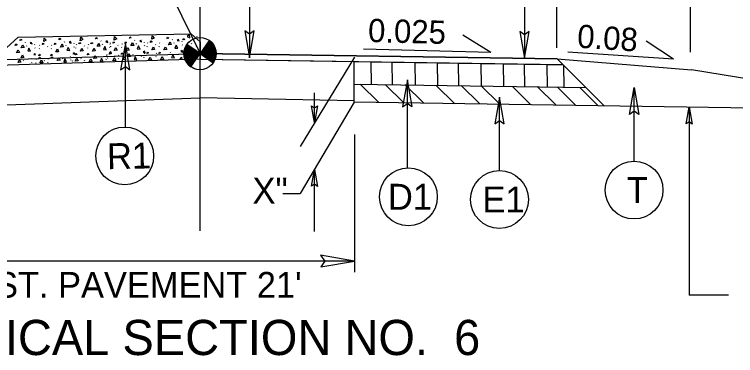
# Model space of a CAD drawing. Extents: x 2176156 to 2177167, y 76401 to 76644.
# Drawn here: x 2177099.84 to 2177132.18, y 76502.12 to 76517.41 of the extents above; entities that cross this region are included whole.
import ezdxf

# ---------------------------------------------------------------- set-up
doc = ezdxf.new("R2010")
doc.units = 0
for name, color, linetype in [('Exist Building', 7, 'Continuous'), ('Exist Building Metal Canopy', 7, 'Continuous'), ('Exist Roads Change in Surface', 7, 'Continuous'), ('Exist Roads Curbs', 7, 'Continuous'), ('Exist Roads EOP Other', 7, 'Continuous'), ('Exist Roads Soil', 7, 'Continuous'), ('Exist Structure Minor Culvert Topo', 7, 'Continuous'), ('Exist Utilities Other Pole CELL', 7, 'Continuous'), ('Model Boundary Lines Text', 7, 'Continuous'), ('Old_Level_1', 7, 'Continuous'), ('Old_Level_3', 7, 'Continuous'), ('Prop North Arrow NAD83 for Plan Sheets CELL', 7, 'Continuous'), ('Sheet Plan CELL', 7, 'Continuous')]:
    doc.layers.add(name, color=color, linetype=linetype)

msp = doc.modelspace()

# ---------------------------------------------------------------- linework, layer by layer
at = {"layer": 'Exist Building'}
for p, q in [((2177115.083, 76513.476), (2177115.083, 76515.298)), ((2177141.279, 76513.086), (2177115.083, 76513.476))]:
    msp.add_line(p, q, dxfattribs=at)
at = {"layer": 'Exist Roads Change in Surface'}
for p, q in [((2177100.315, 76516.153), (2177100.325, 76516.137)), ((2177102.072, 76516.188), (2177102.083, 76516.172)), ((2177102.507, 76516.103), (2177102.496, 76516.087)), ((2177103.714, 76516.221), (2177103.725, 76516.205)), ((2177104.148, 76516.135), (2177104.137, 76516.119)), ((2177105.229, 76516.251), (2177105.24, 76516.235)), ((2177105.664, 76516.166), (2177105.653, 76516.15)), ((2177105.81, 76516.132), (2177105.821, 76516.116)), ((2177106.35, 76516.132), (2177106.36, 76516.116)), ((2177106.918, 76516.285), (2177106.928, 76516.269)), ((2177106.993, 76516.132), (2177106.982, 76516.116)), ((2177107.352, 76516.2), (2177107.341, 76516.184)), ((2177107.788, 76516.08), (2177107.777, 76516.104)), ((2177108.03, 76516.389), (2177108.019, 76516.413)), ((2177108.575, 76516.243), (2177108.163, 76515.651)), ((2177100.39, 76516), (2177100.379, 76515.984)), ((2177100.749, 76516.067), (2177100.738, 76516.051)), ((2177100.769, 76515.892), (2177100.758, 76515.916)), ((2177100.945, 76515.86), (2177100.955, 76515.884)), ((2177100.965, 76516.035), (2177100.976, 76516.019)), ((2177101.324, 76515.967), (2177101.334, 76515.951)), ((2177101.484, 76515.86), (2177101.495, 76515.884)), ((2177101.504, 76516.035), (2177101.515, 76516.019)), ((2177102.148, 76516.035), (2177102.137, 76516.019)), ((2177102.527, 76515.927), (2177102.516, 76515.951)), ((2177102.586, 76515.892), (2177102.597, 76515.916)), ((2177102.607, 76516.068), (2177102.617, 76516.052)), ((2177102.965, 76516), (2177102.976, 76515.984)), ((2177103.126, 76515.892), (2177103.136, 76515.916)), ((2177103.146, 76516.068), (2177103.157, 76516.052)), ((2177103.789, 76516.068), (2177103.779, 76516.052)), ((2177104.102, 76515.923), (2177104.112, 76515.947)), ((2177104.122, 76516.098), (2177104.133, 76516.082)), ((2177104.168, 76515.96), (2177104.158, 76515.984)), ((2177104.481, 76516.03), (2177104.491, 76516.014)), ((2177104.641, 76515.923), (2177104.652, 76515.947)), ((2177104.661, 76516.098), (2177104.672, 76516.082)), ((2177105.305, 76516.098), (2177105.294, 76516.082)), ((2177105.684, 76515.99), (2177105.673, 76516.014)), ((2177105.79, 76515.956), (2177105.801, 76515.98)), ((2177106.169, 76516.064), (2177106.18, 76516.048)), ((2177106.329, 76515.956), (2177106.34, 76515.98)), ((2177107.372, 76516.024), (2177107.361, 76516.048)), ((2177108.163, 76515.651), (2177107.572, 76516.063)), ((2177107.67, 76515.792), (2177107.66, 76515.776)), ((2177108.003, 76515.963), (2177107.993, 76515.987)), ((2177102.355, 76515.52), (2177102.344, 76515.504)), ((2177102.456, 76515.489), (2177102.467, 76515.473)), ((2177102.995, 76515.507), (2177103.006, 76515.492)), ((2177103.638, 76515.528), (2177103.628, 76515.512)), ((2177103.969, 76515.57), (2177103.981, 76515.555)), ((2177103.994, 76515.608), (2177103.984, 76515.592)), ((2177104.02, 76515.433), (2177104.009, 76515.457)), ((2177104.33, 76515.514), (2177104.341, 76515.499)), ((2177104.508, 76515.588), (2177104.52, 76515.573)), ((2177105.151, 76515.61), (2177105.141, 76515.593)), ((2177105.534, 76515.515), (2177105.522, 76515.538)), ((2177105.641, 76515.484), (2177105.651, 76515.509)), ((2177105.655, 76515.661), (2177105.667, 76515.645)), ((2177106.016, 76515.605), (2177106.028, 76515.589)), ((2177106.18, 76515.502), (2177106.19, 76515.527)), ((2177106.195, 76515.679), (2177106.206, 76515.663)), ((2177106.838, 76515.7), (2177106.827, 76515.684)), ((2177107.22, 76515.605), (2177107.209, 76515.628)), ((2177107.752, 76515.059), (2177108.163, 76515.651)), ((2177108.756, 76515.241), (2177108.163, 76515.651)), ((2177108.163, 76515.651), (2177108.756, 76515.241)), ((2177100.243, 76515.347), (2177100.232, 76515.33)), ((2177100.599, 76515.426), (2177100.589, 76515.41)), ((2177100.625, 76515.251), (2177100.614, 76515.275)), ((2177100.802, 76515.225), (2177100.812, 76515.249)), ((2177100.816, 76515.401), (2177100.827, 76515.386)), ((2177101.177, 76515.346), (2177101.188, 76515.33)), ((2177101.341, 76515.243), (2177101.351, 76515.268)), ((2177101.355, 76515.419), (2177101.367, 76515.404)), ((2177101.998, 76515.441), (2177101.988, 76515.424)), ((2177102.381, 76515.346), (2177102.369, 76515.369)), ((2177102.441, 76515.313), (2177102.451, 76515.337)), ((2177102.817, 76515.433), (2177102.828, 76515.418)), ((2177102.981, 76515.331), (2177102.99, 76515.355)), ((2177103.955, 76515.394), (2177103.965, 76515.418)), ((2177104.494, 76515.412), (2177104.504, 76515.436))]:
    msp.add_line(p, q, dxfattribs=at)
for points in [[(2177105.996, 76516.294), (2177106.017, 76516.446), (2177106.112, 76516.347), (2177105.998, 76516.294)], [(2177107.706, 76516.361), (2177107.685, 76516.513), (2177107.589, 76516.415), (2177107.703, 76516.362)], [(2177100.078, 76516.239), (2177100.11, 76516.306), (2177100.163, 76516.266), (2177100.078, 76516.239)], [(2177100.626, 76516.086), (2177100.595, 76516.153), (2177100.541, 76516.113), (2177100.626, 76516.086)], [(2177101.087, 76516.054), (2177101.119, 76516.12), (2177101.172, 76516.08), (2177101.087, 76516.054)], [(2177101.15, 76516.197), (2177101.171, 76516.349), (2177101.267, 76516.25), (2177101.153, 76516.198)], [(2177101.627, 76516.054), (2177101.659, 76516.12), (2177101.712, 76516.08), (2177101.627, 76516.054)], [(2177101.836, 76516.274), (2177101.868, 76516.341), (2177101.921, 76516.301), (2177101.836, 76516.274)], [(2177102.384, 76516.121), (2177102.352, 76516.188), (2177102.299, 76516.148), (2177102.384, 76516.121)], [(2177102.729, 76516.087), (2177102.761, 76516.153), (2177102.814, 76516.113), (2177102.729, 76516.087)], [(2177102.792, 76516.229), (2177102.813, 76516.382), (2177102.908, 76516.283), (2177102.794, 76516.23)], [(2177103.268, 76516.087), (2177103.3, 76516.153), (2177103.353, 76516.113), (2177103.268, 76516.087)], [(2177103.477, 76516.307), (2177103.509, 76516.373), (2177103.563, 76516.334), (2177103.477, 76516.307)], [(2177103.544, 76515.98), (2177103.616, 76516.115), (2177103.672, 76515.99), (2177103.547, 76515.98)], [(2177104.026, 76516.154), (2177103.994, 76516.221), (2177103.941, 76516.181), (2177104.026, 76516.154)], [(2177104.244, 76516.117), (2177104.276, 76516.183), (2177104.329, 76516.143), (2177104.244, 76516.117)], [(2177104.307, 76516.26), (2177104.328, 76516.412), (2177104.424, 76516.314), (2177104.31, 76516.261)], [(2177104.784, 76516.117), (2177104.816, 76516.183), (2177104.869, 76516.143), (2177104.784, 76516.117)], [(2177104.993, 76516.337), (2177105.025, 76516.404), (2177105.078, 76516.364), (2177104.993, 76516.337)], [(2177105.059, 76516.01), (2177105.131, 76516.146), (2177105.187, 76516.021), (2177105.062, 76516.01)], [(2177105.541, 76516.184), (2177105.509, 76516.251), (2177105.456, 76516.211), (2177105.541, 76516.184)], [(2177105.932, 76516.151), (2177105.964, 76516.217), (2177106.018, 76516.177), (2177105.932, 76516.151)], [(2177106.676, 76516.324), (2177106.708, 76516.391), (2177106.761, 76516.351), (2177106.676, 76516.324)], [(2177106.748, 76516.044), (2177106.82, 76516.179), (2177106.875, 76516.054), (2177106.75, 76516.044)], [(2177107.23, 76516.218), (2177107.198, 76516.285), (2177107.144, 76516.245), (2177107.23, 76516.218)], [(2177107.393, 76516.262), (2177107.425, 76516.328), (2177107.478, 76516.288), (2177107.393, 76516.262)], [(2177108.483, 76516.11), (2177108.856, 76515.85)], [(2177108.491, 76516.122), (2177108.85, 76515.872)], [(2177108.499, 76516.134), (2177108.842, 76515.895)], [(2177108.507, 76516.145), (2177108.834, 76515.919)], [(2177108.516, 76516.157), (2177108.823, 76515.943)], [(2177108.524, 76516.169), (2177108.811, 76515.97)], [(2177108.532, 76516.181), (2177108.796, 76515.997)], [(2177108.54, 76516.193), (2177108.78, 76516.026)], [(2177108.549, 76516.205), (2177108.76, 76516.057)], [(2177108.557, 76516.217), (2177108.733, 76516.094)], [(2177108.565, 76516.228), (2177108.699, 76516.135)], [(2177108.573, 76516.24), (2177108.638, 76516.195)], [(2177099.869, 76516.019), (2177099.901, 76516.085), (2177099.954, 76516.045), (2177099.869, 76516.019)], [(2177099.935, 76515.691), (2177100.007, 76515.827), (2177100.063, 76515.702), (2177099.938, 76515.691)], [(2177100.145, 76515.912), (2177100.216, 76516.047), (2177100.272, 76515.922), (2177100.147, 76515.912)], [(2177100.56, 76515.759), (2177100.488, 76515.895), (2177100.432, 76515.769), (2177100.557, 76515.759)], [(2177101.693, 76515.726), (2177101.765, 76515.862), (2177101.821, 76515.737), (2177101.696, 76515.726)], [(2177101.902, 76515.947), (2177101.974, 76516.083), (2177102.03, 76515.957), (2177101.905, 76515.947)], [(2177102.318, 76515.794), (2177102.246, 76515.93), (2177102.19, 76515.805), (2177102.315, 76515.794)], [(2177102.795, 76515.759), (2177102.867, 76515.895), (2177102.923, 76515.77), (2177102.798, 76515.759)], [(2177103.335, 76515.759), (2177103.407, 76515.895), (2177103.463, 76515.77), (2177103.337, 76515.759)], [(2177103.959, 76515.827), (2177103.887, 76515.963), (2177103.831, 76515.837), (2177103.957, 76515.827)], [(2177104.311, 76515.79), (2177104.383, 76515.925), (2177104.439, 76515.8), (2177104.313, 76515.79)], [(2177104.85, 76515.79), (2177104.922, 76515.925), (2177104.978, 76515.8), (2177104.853, 76515.79)], [(2177105.475, 76515.857), (2177105.403, 76515.993), (2177105.347, 76515.868), (2177105.472, 76515.857)], [(2177105.999, 76515.823), (2177106.071, 76515.959), (2177106.127, 76515.834), (2177106.002, 76515.823)], [(2177106.538, 76515.823), (2177106.61, 76515.959), (2177106.666, 76515.834), (2177106.541, 76515.823)], [(2177107.163, 76515.891), (2177107.091, 76516.027), (2177107.035, 76515.901), (2177107.16, 76515.891)], [(2177107.391, 76515.723), (2177107.359, 76515.79), (2177107.305, 76515.75), (2177107.391, 76515.723)], [(2177107.456, 76515.784), (2177107.995, 76515.409)], [(2177107.459, 76515.8), (2177108.003, 76515.421)], [(2177107.462, 76515.815), (2177108.012, 76515.433)], [(2177107.465, 76515.831), (2177108.02, 76515.445)], [(2177107.469, 76515.845), (2177108.028, 76515.457)], [(2177107.474, 76515.86), (2177108.036, 76515.468)], [(2177107.478, 76515.875), (2177108.045, 76515.48)], [(2177107.483, 76515.888), (2177108.053, 76515.492)], [(2177107.488, 76515.903), (2177108.061, 76515.504)], [(2177107.493, 76515.916), (2177108.069, 76515.516)], [(2177107.499, 76515.93), (2177108.077, 76515.528)], [(2177107.504, 76515.944), (2177108.086, 76515.539)], [(2177107.51, 76515.957), (2177108.094, 76515.551)], [(2177107.517, 76515.97), (2177108.102, 76515.563)], [(2177107.524, 76515.983), (2177108.11, 76515.575)], [(2177107.531, 76515.996), (2177108.119, 76515.587)], [(2177107.538, 76516.008), (2177108.127, 76515.599)], [(2177107.545, 76516.021), (2177108.135, 76515.61)], [(2177107.553, 76516.033), (2177108.143, 76515.622)], [(2177107.56, 76516.046), (2177108.152, 76515.634)], [(2177107.568, 76516.058), (2177107.568, 76516.058), (2177108.16, 76515.646)], [(2177108.252, 76515.779), (2177108.829, 76515.377)], [(2177108.26, 76515.79), (2177108.835, 76515.391)], [(2177108.269, 76515.802), (2177108.841, 76515.404)], [(2177108.277, 76515.814), (2177108.845, 76515.419)], [(2177108.285, 76515.826), (2177108.851, 76515.433)], [(2177108.293, 76515.838), (2177108.855, 76515.447)], [(2177108.302, 76515.85), (2177108.859, 76515.462)], [(2177108.31, 76515.862), (2177108.863, 76515.476)], [(2177108.318, 76515.873), (2177108.866, 76515.492)], [(2177108.326, 76515.885), (2177108.869, 76515.507)], [(2177108.335, 76515.897), (2177108.872, 76515.523)], [(2177108.343, 76515.909), (2177108.875, 76515.538)], [(2177108.351, 76515.921), (2177108.878, 76515.554)], [(2177108.359, 76515.932), (2177108.88, 76515.57)], [(2177108.368, 76515.944), (2177108.882, 76515.587)], [(2177108.376, 76515.956), (2177108.883, 76515.603)], [(2177108.384, 76515.968), (2177108.884, 76515.62)], [(2177108.392, 76515.98), (2177108.884, 76515.638)], [(2177108.4, 76515.992), (2177108.884, 76515.655)], [(2177108.409, 76516.003), (2177108.885, 76515.672)], [(2177108.417, 76516.015), (2177108.884, 76515.69)], [(2177108.425, 76516.027), (2177108.883, 76515.709)], [(2177108.433, 76516.039), (2177108.88, 76515.728)], [(2177108.442, 76516.051), (2177108.878, 76515.747)], [(2177108.45, 76516.063), (2177108.876, 76515.766)], [(2177108.458, 76516.075), (2177108.872, 76515.786)], [(2177108.466, 76516.086), (2177108.867, 76515.807)], [(2177108.475, 76516.098), (2177108.862, 76515.828)], [(2177100.134, 76515.461), (2177100.206, 76515.597), (2177100.262, 76515.471), (2177100.136, 76515.461)], [(2177100.788, 76515.591), (2177100.756, 76515.657), (2177100.702, 76515.617), (2177100.788, 76515.591)], [(2177100.926, 76515.559), (2177100.958, 76515.625), (2177101.011, 76515.585), (2177100.926, 76515.559)], [(2177100.938, 76515.424), (2177100.967, 76515.492), (2177101.022, 76515.453), (2177100.938, 76515.424)], [(2177101.466, 76515.559), (2177101.498, 76515.625), (2177101.551, 76515.585), (2177101.466, 76515.559)], [(2177101.477, 76515.442), (2177101.507, 76515.51), (2177101.561, 76515.471), (2177101.477, 76515.442)], [(2177101.756, 76515.344), (2177101.823, 76515.482), (2177101.883, 76515.359), (2177101.759, 76515.344)], [(2177102.545, 76515.626), (2177102.513, 76515.693), (2177102.46, 76515.653), (2177102.545, 76515.626)], [(2177102.568, 76515.591), (2177102.6, 76515.658), (2177102.653, 76515.618), (2177102.568, 76515.591)], [(2177103.107, 76515.591), (2177103.139, 76515.658), (2177103.192, 76515.618), (2177103.107, 76515.591)], [(2177103.396, 76515.432), (2177103.463, 76515.57), (2177103.523, 76515.447), (2177103.398, 76515.432)], [(2177104.083, 76515.622), (2177104.115, 76515.688), (2177104.168, 76515.648), (2177104.083, 76515.622)], [(2177104.187, 76515.659), (2177104.155, 76515.725), (2177104.102, 76515.685), (2177104.187, 76515.659)], [(2177104.257, 76515.326), (2177104.325, 76515.464), (2177104.385, 76515.341), (2177104.26, 76515.326)], [(2177104.623, 76515.622), (2177104.655, 76515.688), (2177104.708, 76515.648), (2177104.623, 76515.622)], [(2177104.707, 76515.367), (2177104.775, 76515.505), (2177104.835, 76515.382), (2177104.71, 76515.367)], [(2177104.909, 76515.513), (2177104.976, 76515.651), (2177105.037, 76515.528), (2177104.912, 76515.513)], [(2177105.329, 76515.374), (2177105.253, 76515.508), (2177105.201, 76515.381), (2177105.327, 76515.374)], [(2177105.702, 76515.689), (2177105.67, 76515.756), (2177105.617, 76515.716), (2177105.702, 76515.689)], [(2177105.771, 76515.655), (2177105.803, 76515.722), (2177105.857, 76515.682), (2177105.771, 76515.655)], [(2177105.855, 76515.358), (2177105.922, 76515.496), (2177105.982, 76515.373), (2177105.857, 76515.358)], [(2177106.311, 76515.655), (2177106.343, 76515.722), (2177106.396, 76515.682), (2177106.311, 76515.655)], [(2177106.394, 76515.376), (2177106.461, 76515.515), (2177106.521, 76515.391), (2177106.396, 76515.376)], [(2177107.016, 76515.465), (2177106.939, 76515.598), (2177106.887, 76515.471), (2177107.013, 76515.465)], [(2177107.281, 76515.422), (2177107.313, 76515.489), (2177107.367, 76515.449), (2177107.281, 76515.422)], [(2177107.443, 76515.688), (2177107.946, 76515.338)], [(2177107.443, 76515.67), (2177107.937, 76515.326)], [(2177107.443, 76515.653), (2177107.929, 76515.315)], [(2177107.443, 76515.618), (2177107.913, 76515.291)], [(2177107.444, 76515.635), (2177107.921, 76515.303)], [(2177107.444, 76515.599), (2177107.904, 76515.279)], [(2177107.445, 76515.704), (2177107.954, 76515.35)], [(2177107.447, 76515.721), (2177107.962, 76515.362)], [(2177107.447, 76515.58), (2177107.896, 76515.267)], [(2177107.448, 76515.737), (2177107.97, 76515.374)], [(2177107.449, 76515.561), (2177107.888, 76515.255)], [(2177107.45, 76515.753), (2177107.979, 76515.385)], [(2177107.451, 76515.542), (2177107.88, 76515.244)], [(2177107.453, 76515.769), (2177107.987, 76515.397)], [(2177107.455, 76515.522), (2177107.872, 76515.232)], [(2177107.458, 76515.502), (2177107.863, 76515.22)], [(2177107.463, 76515.481), (2177107.855, 76515.208)], [(2177107.469, 76515.459), (2177107.847, 76515.196)], [(2177108.17, 76515.66), (2177108.762, 76515.249), (2177108.762, 76515.249)], [(2177108.178, 76515.672), (2177108.77, 76515.26)], [(2177108.186, 76515.684), (2177108.777, 76515.273)], [(2177108.195, 76515.696), (2177108.785, 76515.285)], [(2177108.203, 76515.708), (2177108.792, 76515.298)], [(2177108.211, 76515.719), (2177108.799, 76515.311)], [(2177108.219, 76515.731), (2177108.806, 76515.323)], [(2177108.228, 76515.743), (2177108.811, 76515.337)], [(2177108.236, 76515.755), (2177108.818, 76515.35)], [(2177108.244, 76515.767), (2177108.824, 76515.363)], [(2177100, 76515.25), (2177100.068, 76515.388), (2177100.128, 76515.265), (2177100.003, 76515.25)], [(2177100.981, 76515.233), (2177101.053, 76515.369), (2177101.109, 76515.243), (2177100.983, 76515.233)], [(2177102.176, 76515.279), (2177102.1, 76515.413), (2177102.048, 76515.286), (2177102.174, 76515.279)], [(2177102.568, 76515.31), (2177102.635, 76515.448), (2177102.695, 76515.325), (2177102.57, 76515.31)], [(2177103.194, 76515.285), (2177103.261, 76515.423), (2177103.321, 76515.299), (2177103.197, 76515.285)], [(2177103.816, 76515.293), (2177103.739, 76515.427), (2177103.688, 76515.3), (2177103.813, 76515.293)], [(2177107.476, 76515.437), (2177107.839, 76515.184)], [(2177107.483, 76515.414), (2177107.83, 76515.173)], [(2177107.492, 76515.39), (2177107.822, 76515.161)], [(2177107.502, 76515.366), (2177107.814, 76515.149)], [(2177107.514, 76515.34), (2177107.806, 76515.137)], [(2177107.527, 76515.314), (2177107.797, 76515.125)], [(2177107.543, 76515.284), (2177107.789, 76515.113)], [(2177107.563, 76515.253), (2177107.781, 76515.102)], [(2177107.587, 76515.219), (2177107.773, 76515.09)], [(2177107.62, 76515.179), (2177107.765, 76515.078)], [(2177107.672, 76515.125), (2177107.756, 76515.066)]]:
    msp.add_lwpolyline(points, dxfattribs=at)
msp.add_circle((2177108.164, 76515.652), 0.721, dxfattribs=at)
for start, end in [(325.1751, 55.1751), (145.1751, 235.1751)]:
    msp.add_arc((2177108.164, 76515.652), 0.721, start, end, dxfattribs=at)
at = {"layer": 'Exist Roads Curbs'}
for p, q in [((2177099.488, 76515.381), (2177108.163, 76515.651)), ((2177108.163, 76515.651), (2177124.177, 76515.413)), ((2177124.176, 76515.414), (2177108.163, 76515.651)), ((2177108.163, 76515.651), (2177108.163, 76515.401)), ((2177108.163, 76515.401), (2177083.187, 76514.622)), ((2177108.163, 76515.401), (2177124.432, 76515.159)), ((2177123.731, 76515.171), (2177123.731, 76515.17)), ((2177123.731, 76515.17), (2177124.432, 76515.159)), ((2177124.432, 76515.159), (2177124.176, 76515.414))]:
    msp.add_line(p, q, dxfattribs=at)
for points in [[(2177108.163, 76515.401), (2177115.083, 76515.298), (2177115.845, 76515.287), (2177116.785, 76515.273), (2177117.818, 76515.258), (2177118.816, 76515.243), (2177119.756, 76515.229), (2177120.776, 76515.214), (2177121.773, 76515.199), (2177122.713, 76515.185), (2177123.731, 76515.17)], [(2177123.731, 76515.17), (2177123.731, 76515.171)]]:
    msp.add_lwpolyline(points, dxfattribs=at)
at = {"layer": 'Exist Roads EOP Other'}
msp.add_line((2177124.176, 76515.414), (2177130.212, 76514.931), dxfattribs=at)
at = {"layer": 'Exist Roads Soil'}
for p, q in [((2177100.005, 76516.388), (2177107.772, 76516.543)), ((2177108.163, 76516.182), (2177107.772, 76516.543)), ((2177099.488, 76515.912), (2177100.005, 76516.388)), ((2177108.163, 76516.182), (2177108.163, 76515.401)), ((2177124.176, 76515.414), (2177126.293, 76513.309)), ((2177158.163, 76510.272), (2177130.212, 76514.931)), ((2177115.095, 76514.282), (2177125.47, 76514.128))]:
    msp.add_line(p, q, dxfattribs=at)
at = {"layer": 'Exist Utilities Other Pole CELL'}
for p, q in [((2177121.213, 76515.706), (2177119.957, 76516.476)), ((2177129.404, 76515.397), (2177128.179, 76516.216)), ((2177121.213, 76515.706), (2177115.488, 76515.856)), ((2177129.404, 76515.397), (2177124.658, 76515.71))]:
    msp.add_line(p, q, dxfattribs=at)
at = {"layer": 'Model Boundary Lines Text'}
for p, q in [((2177115.86, 76514.273), (2177115.845, 76515.298)), ((2177116.8, 76514.265), (2177116.785, 76515.279)), ((2177117.833, 76514.252), (2177117.818, 76515.264)), ((2177118.83, 76514.228), (2177118.815, 76515.254)), ((2177119.77, 76514.221), (2177119.756, 76515.235)), ((2177120.79, 76514.2), (2177120.776, 76515.211)), ((2177121.788, 76514.176), (2177121.773, 76515.201)), ((2177122.728, 76514.169), (2177122.713, 76515.182)), ((2177123.746, 76514.155), (2177123.731, 76515.171)), ((2177124.489, 76514.142), (2177124.475, 76515.116)), ((2177116.182, 76513.455), (2177115.341, 76514.278)), ((2177117.301, 76513.451), (2177116.466, 76514.269)), ((2177118.186, 76513.447), (2177117.35, 76514.266)), ((2177119.594, 76513.406), (2177118.758, 76514.225)), ((2177120.713, 76513.402), (2177119.877, 76514.221)), ((2177121.599, 76513.397), (2177120.764, 76514.215)), ((2177123.007, 76513.356), (2177122.172, 76514.174)), ((2177124.127, 76513.352), (2177123.291, 76514.171)), ((2177125.02, 76513.333), (2177124.193, 76514.144)), ((2177126.01, 76513.333), (2177125.195, 76514.132))]:
    msp.add_line(p, q, dxfattribs=at)
at = {"layer": 'Old_Level_1'}
for points in [[(2177113.428, 76513.313), (2177113.295, 76512.559), (2177113.163, 76513.318), (2177113.297, 76513.221)], [(2177129.966, 76512.498), (2177130.096, 76513.252), (2177130.23, 76512.493), (2177130.096, 76512.59)], [(2177113.163, 76509.703), (2177113.295, 76510.457), (2177113.427, 76509.698), (2177113.293, 76509.794)], [(2177113.576, 76506.092), (2177115.086, 76506.352), (2177113.568, 76506.62), (2177113.761, 76506.352)]]:
    msp.add_lwpolyline(points, close=True, dxfattribs=at)
at = {"layer": 'Old_Level_3'}
for p, q in [((2177130.163, 76515.709), (2177130.163, 76530.14)), ((2177108.163, 76507.712), (2177108.163, 76526.159)), ((2177124.163, 76515.918), (2177124.163, 76524.993)), ((2177115.084, 76515.491), (2177112.658, 76511.483)), ((2177113.295, 76512.559), (2177113.295, 76513.887)), ((2177115.083, 76513.476), (2177112.658, 76509.382)), ((2177130.096, 76513.252), (2177130.096, 76504.827)), ((2177115.086, 76512.024), (2177115.086, 76505.861)), ((2177113.295, 76507.681), (2177113.295, 76510.457)), ((2177111.878, 76509.382), (2177112.658, 76509.382)), ((2177115.086, 76506.352), (2177091.306, 76506.352)), ((2177131.863, 76504.827), (2177130.096, 76504.827))]:
    msp.add_line(p, q, dxfattribs=at)
at = {"layer": 'Prop North Arrow NAD83 for Plan Sheets CELL'}
for p, q in [((2177105.44, 76521.259), (2177108.163, 76515.651)), ((2177122.711, 76519.744), (2177122.711, 76515.442)), ((2177110.374, 76518.601), (2177110.374, 76515.468)), ((2177104.812, 76512.36), (2177104.812, 76516.125)), ((2177117.463, 76510.53), (2177117.463, 76514.475)), ((2177127.63, 76510.831), (2177127.63, 76514.126)), ((2177121.592, 76510.407), (2177121.592, 76513.703))]:
    msp.add_line(p, q, dxfattribs=at)
for points in [[(2177110.168, 76516.668), (2177110.374, 76515.468), (2177110.588, 76516.674), (2177110.374, 76516.521)], [(2177122.504, 76516.642), (2177122.711, 76515.442), (2177122.924, 76516.648), (2177122.711, 76516.495)], [(2177105.019, 76514.925), (2177104.812, 76516.125), (2177104.599, 76514.919), (2177104.812, 76515.072)], [(2177117.67, 76513.275), (2177117.463, 76514.475), (2177117.25, 76513.268), (2177117.463, 76513.421)], [(2177127.423, 76512.926), (2177127.63, 76514.126), (2177127.843, 76512.92), (2177127.63, 76513.073)], [(2177121.799, 76512.503), (2177121.592, 76513.703), (2177121.379, 76512.497), (2177121.592, 76512.65)]]:
    msp.add_lwpolyline(points, close=True, dxfattribs=at)
for centre in [(2177104.785, 76511.065), (2177127.63, 76509.535), (2177117.509, 76509.235), (2177121.592, 76509.111)]:
    msp.add_circle(centre, 1.296, dxfattribs=at)
at = {"layer": 'Sheet Plan CELL'}
for p in [(2177091.306, 76513.06), (2177115.083, 76513.528)]:
    msp.add_line(p, (2177108.163, 76513.671), dxfattribs=at)

# ---------------------------------------------------------------- texts
at = {"layer": 'Exist Building Metal Canopy'}
msp.add_text('TYPICAL SECTION NO.  6', height=1.5766, rotation=0, dxfattribs=at).set_placement((2177095.309, 76502.14))
at = {"layer": 'Exist Structure Minor Culvert Topo'}
msp.add_text("EXIST. PAVEMENT 21'", height=1.15334, dxfattribs=at).set_placement((2177096.483, 76504.711))
at = {"layer": 'Exist Utilities Other Pole CELL'}
for s, rotation, p in [('0.025', 358.5068, (2177115.689, 76516.173)), ('0.08', 356.2199, (2177125.054, 76515.921))]:
    msp.add_text(s, height=1.0429, rotation=rotation, dxfattribs=at).set_placement(p)
at = {"layer": 'Prop North Arrow NAD83 for Plan Sheets CELL'}
for s, rotation, p in [('R1', 1.1751, (2177104, 76510.468)), ('T', 0.0003, (2177127.303, 76508.955)), ('D1', 359.9997, (2177116.588, 76508.655)), ('E1', 359.9997, (2177120.829, 76508.531))]:
    msp.add_text(s, height=1.16, rotation=rotation, dxfattribs=at).set_placement(p)
msp.add_text('X"', height=1.1533, dxfattribs=at).set_placement((2177110.517, 76508.932))

doc.saveas('drawing.dxf')
